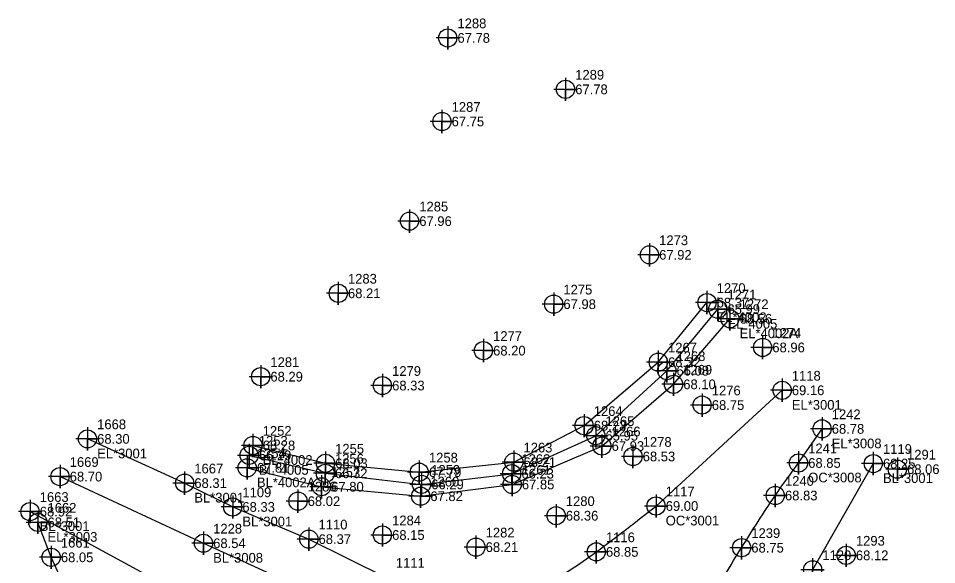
# Model space of a CAD drawing. Extents: x 2062781 to 2066835, y 358981 to 366501.
# Drawn here: x 2066377.3 to 2066613.7, y 366359.8 to 366500.5 of the extents above; entities that cross this region are included whole.
import ezdxf

# ---------------------------------------------------------------- set-up
doc = ezdxf.new("R2010")
doc.units = 0
for name, color, linetype in [('Exist DTM Breakline', 7, 'Continuous'), ('Exist DTM Breakline Cogo Comment', 7, 'Continuous'), ('Exist DTM Breakline Cogo Elevation', 7, 'Continuous'), ('Exist DTM Breakline Cogo Number', 7, 'Continuous'), ('Exist DTM Breakline Cogo Point CELL', 7, 'Continuous'), ('Exist DTM Crownline', 7, 'Continuous'), ('Exist DTM Crownline Cogo Comment', 7, 'Continuous'), ('Exist DTM Crownline Cogo Elevation', 7, 'Continuous'), ('Exist DTM Crownline Cogo Number', 7, 'Continuous'), ('Exist DTM Crownline Cogo Point CELL', 7, 'Continuous'), ('Exist DTM Regular Point CELL', 7, 'Continuous'), ('Exist DTM Regular Point Cogo Elevation', 7, 'Continuous'), ('Exist DTM Regular Point Cogo Number', 7, 'Continuous'), ('Exist DTM Ridgeline', 7, 'Continuous'), ('Exist DTM Ridgeline Cogo Comment', 7, 'Continuous'), ('Exist DTM Ridgeline Cogo Elevation', 7, 'Continuous'), ('Exist DTM Ridgeline Cogo Number', 7, 'Continuous'), ('Exist DTM Ridgeline Cogo Point CELL', 7, 'Continuous'), ('Exist Roads EOP', 7, 'Continuous'), ('Exist Roads EOP Cogo Comment', 7, 'Continuous'), ('Exist Roads EOP Cogo Elevation', 7, 'Continuous'), ('Exist Roads EOP Cogo Number', 7, 'Continuous'), ('Exist Roads EOP Cogo Point CELL', 7, 'Continuous'), ('Exist Roads EOP Other', 7, 'Continuous'), ('Exist Roads EOP Other Cogo Comment', 7, 'Continuous'), ('Exist Roads EOP Other Cogo Elevation', 7, 'Continuous'), ('Exist Roads EOP Other Cogo Number', 7, 'Continuous'), ('Exist Roads EOP Other Cogo Point CELL', 7, 'Continuous')]:
    doc.layers.add(name, color=color, linetype=linetype)

msp = doc.modelspace()

# ---------------------------------------------------------------- linework, layer by layer
at = {"layer": 'Exist DTM Breakline'}
msp.add_lwpolyline([(2066436.74, 366387.93), (2066456.35, 366383.31), (2066481.14, 366380.45), (2066504.34, 366383.21), (2066525.99, 366392.99), (2066544.27, 366409.73), (2066557.39, 366425.59)], dxfattribs=at)
at = {"layer": 'Exist DTM Breakline Cogo Point CELL'}
for points in [[(2066557.39, 366428.59), (2066557.39, 366422.59), (2066557.39, 366425.59), (2066560.39, 366425.59), (2066554.39, 366425.59)], [(2066544.27, 366412.73), (2066544.27, 366406.73), (2066544.27, 366409.73), (2066547.27, 366409.73), (2066541.27, 366409.73)], [(2066525.99, 366395.99), (2066525.99, 366389.99), (2066525.99, 366392.99), (2066528.99, 366392.99), (2066522.99, 366392.99)], [(2066436.74, 366390.93), (2066436.74, 366384.93), (2066436.74, 366387.93), (2066439.74, 366387.93), (2066433.74, 366387.93)], [(2066456.35, 366386.31), (2066456.35, 366380.31), (2066456.35, 366383.31), (2066459.35, 366383.31), (2066453.35, 366383.31)], [(2066504.34, 366386.21), (2066504.34, 366380.21), (2066504.34, 366383.21), (2066507.34, 366383.21), (2066501.34, 366383.21)], [(2066481.14, 366383.45), (2066481.14, 366377.45), (2066481.14, 366380.45), (2066484.14, 366380.45), (2066478.14, 366380.45)]]:
    msp.add_lwpolyline(points, dxfattribs=at)
for centre in [(2066557.39, 366425.59), (2066544.27, 366409.73), (2066525.99, 366392.99), (2066436.74, 366387.93), (2066456.35, 366383.31), (2066504.34, 366383.21), (2066481.14, 366380.45)]:
    msp.add_circle(centre, 2.34, dxfattribs=at)
at = {"layer": 'Exist DTM Crownline'}
msp.add_line((2066578.18, 366385.97), (2066584.24, 366394.75), dxfattribs=at)
for points in [[(2066388.06, 366382.46), (2066424.99, 366365.29)], [(2066424.99, 366365.29), (2066467.59, 366345.83), (2066505.51, 366328.48), (2066538.44, 366313.65), (2066572.05, 366298.64), (2066616.11, 366278.59), (2066645.68, 366265.08), (2066686.23, 366246.88)]]:
    msp.add_lwpolyline(points, dxfattribs=at)
msp.add_spline([(2066545.84, 366333.5), (2066552.89, 366346.31), (2066563.53, 366364.14), (2066572.2, 366377.58), (2066578.18, 366385.97)], degree=3, dxfattribs=at)
at = {"layer": 'Exist DTM Crownline Cogo Point CELL'}
for points in [[(2066584.24, 366397.75), (2066584.24, 366391.75), (2066584.24, 366394.75), (2066587.24, 366394.75), (2066581.24, 366394.75)], [(2066578.18, 366388.97), (2066578.18, 366382.97), (2066578.18, 366385.97), (2066581.18, 366385.97), (2066575.18, 366385.97)], [(2066388.06, 366385.46), (2066388.06, 366379.46), (2066388.06, 366382.46), (2066391.06, 366382.46), (2066385.06, 366382.46)], [(2066572.2, 366380.58), (2066572.2, 366374.58), (2066572.2, 366377.58), (2066575.2, 366377.58), (2066569.2, 366377.58)], [(2066424.99, 366368.29), (2066424.99, 366362.29), (2066424.99, 366365.29), (2066427.99, 366365.29), (2066421.99, 366365.29)], [(2066563.53, 366367.14), (2066563.53, 366361.14), (2066563.53, 366364.14), (2066566.53, 366364.14), (2066560.53, 366364.14)]]:
    msp.add_lwpolyline(points, dxfattribs=at)
for centre in [(2066584.24, 366394.75), (2066578.18, 366385.97), (2066388.06, 366382.46), (2066572.2, 366377.58), (2066424.99, 366365.29), (2066563.53, 366364.14)]:
    msp.add_circle(centre, 2.34, dxfattribs=at)
at = {"layer": 'Exist DTM Regular Point CELL'}
for points in [[(2066487.88, 366498.48), (2066487.88, 366492.48), (2066487.88, 366495.48), (2066490.88, 366495.48), (2066484.88, 366495.48)], [(2066518.2, 366485.23), (2066518.2, 366479.23), (2066518.2, 366482.23), (2066521.2, 366482.23), (2066515.2, 366482.23)], [(2066486.38, 366476.94), (2066486.38, 366470.94), (2066486.38, 366473.94), (2066489.38, 366473.94), (2066483.38, 366473.94)], [(2066478.05, 366451.28), (2066478.05, 366445.28), (2066478.05, 366448.28), (2066481.05, 366448.28), (2066475.05, 366448.28)], [(2066539.81, 366442.59), (2066539.81, 366436.59), (2066539.81, 366439.59), (2066542.81, 366439.59), (2066536.81, 366439.59)], [(2066459.69, 366432.68), (2066459.69, 366426.68), (2066459.69, 366429.68), (2066462.69, 366429.68), (2066456.69, 366429.68)], [(2066515.15, 366429.88), (2066515.15, 366423.88), (2066515.15, 366426.88), (2066518.15, 366426.88), (2066512.15, 366426.88)], [(2066497.06, 366417.91), (2066497.06, 366411.91), (2066497.06, 366414.91), (2066500.06, 366414.91), (2066494.06, 366414.91)], [(2066568.94, 366418.73), (2066568.94, 366412.73), (2066568.94, 366415.73), (2066571.94, 366415.73), (2066565.94, 366415.73)], [(2066439.72, 366411.2), (2066439.72, 366405.2), (2066439.72, 366408.2), (2066442.72, 366408.2), (2066436.72, 366408.2)], [(2066471.06, 366408.91), (2066471.06, 366402.91), (2066471.06, 366405.91), (2066474.06, 366405.91), (2066468.06, 366405.91)], [(2066553.36, 366403.89), (2066553.36, 366397.89), (2066553.36, 366400.89), (2066556.36, 366400.89), (2066550.36, 366400.89)], [(2066535.57, 366390.64), (2066535.57, 366384.64), (2066535.57, 366387.64), (2066538.57, 366387.64), (2066532.57, 366387.64)], [(2066603.63, 366387.36), (2066603.63, 366381.36), (2066603.63, 366384.36), (2066606.63, 366384.36), (2066600.63, 366384.36)], [(2066449.32, 366379.13), (2066449.32, 366373.13), (2066449.32, 366376.13), (2066452.32, 366376.13), (2066446.32, 366376.13)], [(2066515.78, 366375.38), (2066515.78, 366369.38), (2066515.78, 366372.38), (2066518.78, 366372.38), (2066512.78, 366372.38)], [(2066471.06, 366370.41), (2066471.06, 366364.41), (2066471.06, 366367.41), (2066474.06, 366367.41), (2066468.06, 366367.41)], [(2066495.14, 366367.28), (2066495.14, 366361.28), (2066495.14, 366364.28), (2066498.14, 366364.28), (2066492.14, 366364.28)], [(2066590.46, 366365.17), (2066590.46, 366359.17), (2066590.46, 366362.17), (2066593.46, 366362.17), (2066587.46, 366362.17)]]:
    msp.add_lwpolyline(points, dxfattribs=at)
for centre in [(2066487.88, 366495.48), (2066518.2, 366482.23), (2066486.38, 366473.94), (2066478.05, 366448.28), (2066539.81, 366439.59), (2066459.69, 366429.68), (2066515.15, 366426.88), (2066497.06, 366414.91), (2066568.94, 366415.73), (2066439.72, 366408.2), (2066471.06, 366405.91), (2066553.36, 366400.89), (2066535.57, 366387.64), (2066603.63, 366384.36), (2066449.32, 366376.13), (2066515.78, 366372.38), (2066471.06, 366367.41), (2066495.14, 366364.28), (2066590.46, 366362.17)]:
    msp.add_circle(centre, 2.34, dxfattribs=at)
at = {"layer": 'Exist DTM Ridgeline'}
for points in [[(2066437.74, 366390.48), (2066456.4, 366385.89), (2066480.54, 366383.59), (2066504.88, 366386.18), (2066522.97, 366395.58), (2066542.09, 366411.94), (2066554.62, 366427.28)], [(2066436.25, 366384.72), (2066455.38, 366379.84), (2066480.9, 366377.4), (2066504.46, 366380.42), (2066527.57, 366390.33), (2066546.01, 366406.23), (2066560.52, 366423.12)]]:
    msp.add_lwpolyline(points, dxfattribs=at)
at = {"layer": 'Exist DTM Ridgeline Cogo Point CELL'}
for points in [[(2066554.62, 366430.28), (2066554.62, 366424.28), (2066554.62, 366427.28), (2066557.62, 366427.28), (2066551.62, 366427.28)], [(2066560.52, 366426.12), (2066560.52, 366420.12), (2066560.52, 366423.12), (2066563.52, 366423.12), (2066557.52, 366423.12)], [(2066542.09, 366414.94), (2066542.09, 366408.94), (2066542.09, 366411.94), (2066545.09, 366411.94), (2066539.09, 366411.94)], [(2066546.01, 366409.23), (2066546.01, 366403.23), (2066546.01, 366406.23), (2066549.01, 366406.23), (2066543.01, 366406.23)], [(2066522.97, 366398.58), (2066522.97, 366392.58), (2066522.97, 366395.58), (2066525.97, 366395.58), (2066519.97, 366395.58)], [(2066437.74, 366393.48), (2066437.74, 366387.48), (2066437.74, 366390.48), (2066440.74, 366390.48), (2066434.74, 366390.48)], [(2066527.57, 366393.33), (2066527.57, 366387.33), (2066527.57, 366390.33), (2066530.57, 366390.33), (2066524.57, 366390.33)], [(2066456.4, 366388.89), (2066456.4, 366382.89), (2066456.4, 366385.89), (2066459.4, 366385.89), (2066453.4, 366385.89)], [(2066504.88, 366389.18), (2066504.88, 366383.18), (2066504.88, 366386.18), (2066507.88, 366386.18), (2066501.88, 366386.18)], [(2066436.25, 366387.72), (2066436.25, 366381.72), (2066436.25, 366384.72), (2066439.25, 366384.72), (2066433.25, 366384.72)], [(2066480.54, 366386.59), (2066480.54, 366380.59), (2066480.54, 366383.59), (2066483.54, 366383.59), (2066477.54, 366383.59)], [(2066455.38, 366382.84), (2066455.38, 366376.84), (2066455.38, 366379.84), (2066458.38, 366379.84), (2066452.38, 366379.84)], [(2066504.46, 366383.42), (2066504.46, 366377.42), (2066504.46, 366380.42), (2066507.46, 366380.42), (2066501.46, 366380.42)], [(2066480.9, 366380.4), (2066480.9, 366374.4), (2066480.9, 366377.4), (2066483.9, 366377.4), (2066477.9, 366377.4)]]:
    msp.add_lwpolyline(points, dxfattribs=at)
for centre in [(2066554.62, 366427.28), (2066560.52, 366423.12), (2066542.09, 366411.94), (2066546.01, 366406.23), (2066522.97, 366395.58), (2066437.74, 366390.48), (2066527.57, 366390.33), (2066436.25, 366384.72), (2066456.4, 366385.89), (2066504.88, 366386.18), (2066480.54, 366383.59), (2066455.38, 366379.84), (2066504.46, 366380.42), (2066480.9, 366377.4)]:
    msp.add_circle(centre, 2.34, dxfattribs=at)
at = {"layer": 'Exist Roads EOP'}
for p, q in [((2066541.5, 366374.88), (2066573.97, 366404.69)), ((2066420.14, 366380.78), (2066395.12, 366392.17)), ((2066597.43, 366385.81), (2066581.82, 366358.44)), ((2066380.34, 366373.44), (2066417.22, 366353.45))]:
    msp.add_line(p, q, dxfattribs=at)
for points in [[(2066420.14, 366380.78), (2066432.51, 366374.63)], [(2066432.51, 366374.63), (2066452.12, 366366.34), (2066472.03, 366356.47), (2066473.74, 366354.05)]]:
    msp.add_lwpolyline(points, dxfattribs=at)
msp.add_spline([(2066473.74, 366354.05), (2066483.78, 366350.74), (2066499.41, 366351.53), (2066512.07, 366354.63), (2066526.11, 366363.06), (2066541.5, 366374.88)], degree=3, dxfattribs=at)
at = {"layer": 'Exist Roads EOP Cogo Point CELL'}
for points in [[(2066573.97, 366407.69), (2066573.97, 366401.69), (2066573.97, 366404.69), (2066576.97, 366404.69), (2066570.97, 366404.69)], [(2066395.12, 366395.17), (2066395.12, 366389.17), (2066395.12, 366392.17), (2066398.12, 366392.17), (2066392.12, 366392.17)], [(2066597.43, 366388.81), (2066597.43, 366382.81), (2066597.43, 366385.81), (2066600.43, 366385.81), (2066594.43, 366385.81)], [(2066420.14, 366383.78), (2066420.14, 366377.78), (2066420.14, 366380.78), (2066423.14, 366380.78), (2066417.14, 366380.78)], [(2066432.51, 366377.63), (2066432.51, 366371.63), (2066432.51, 366374.63), (2066435.51, 366374.63), (2066429.51, 366374.63)], [(2066541.5, 366377.88), (2066541.5, 366371.88), (2066541.5, 366374.88), (2066544.5, 366374.88), (2066538.5, 366374.88)], [(2066380.34, 366376.44), (2066380.34, 366370.44), (2066380.34, 366373.44), (2066383.34, 366373.44), (2066377.34, 366373.44)], [(2066452.12, 366369.34), (2066452.12, 366363.34), (2066452.12, 366366.34), (2066455.12, 366366.34), (2066449.12, 366366.34)], [(2066526.11, 366366.06), (2066526.11, 366360.06), (2066526.11, 366363.06), (2066529.11, 366363.06), (2066523.11, 366363.06)], [(2066581.82, 366361.44), (2066581.82, 366355.44), (2066581.82, 366358.44), (2066584.82, 366358.44), (2066578.82, 366358.44)]]:
    msp.add_lwpolyline(points, dxfattribs=at)
for centre in [(2066573.97, 366404.69), (2066395.12, 366392.17), (2066597.43, 366385.81), (2066420.14, 366380.78), (2066541.5, 366374.88), (2066380.34, 366373.44), (2066432.51, 366374.63), (2066452.12, 366366.34), (2066526.11, 366363.06), (2066581.82, 366358.44)]:
    msp.add_circle(centre, 2.34, dxfattribs=at)
at = {"layer": 'Exist Roads EOP Other'}
msp.add_lwpolyline([(2066389.42, 366353.58), (2066389.1, 366354.32), (2066385.78, 366361.66), (2066382.35, 366370.67)], dxfattribs=at)
at = {"layer": 'Exist Roads EOP Other Cogo Point CELL'}
for points in [[(2066382.35, 366373.67), (2066382.35, 366367.67), (2066382.35, 366370.67), (2066385.35, 366370.67), (2066379.35, 366370.67)], [(2066385.78, 366364.66), (2066385.78, 366358.66), (2066385.78, 366361.66), (2066388.78, 366361.66), (2066382.78, 366361.66)]]:
    msp.add_lwpolyline(points, dxfattribs=at)
for centre in [(2066382.35, 366370.67), (2066385.78, 366361.66)]:
    msp.add_circle(centre, 2.34, dxfattribs=at)

# ---------------------------------------------------------------- texts
at = {"layer": 'Exist DTM Breakline Cogo Comment'}
for s, p in [('EL*4005', (2066559.89, 366420.59)), ('BL*4005', (2066439.24, 366382.93))]:
    msp.add_text(s, height=2.5, dxfattribs=at).set_placement(p)
at = {"layer": 'Exist DTM Breakline Cogo Elevation'}
for s, p in [('65.99', (2066559.89, 366424.34)), ('66.08', (2066546.77, 366408.48)), ('65.95', (2066528.49, 366391.74)), ('66.29', (2066439.24, 366386.68)), ('66.32', (2066458.85, 366382.06)), ('66.23', (2066506.84, 366381.96)), ('66.29', (2066483.64, 366379.2))]:
    msp.add_text(s, height=2.5, dxfattribs=at).set_placement(p)
at = {"layer": 'Exist DTM Breakline Cogo Number'}
for s, p in [('1271', (2066559.89, 366428.09)), ('1268', (2066546.77, 366412.23)), ('1265', (2066528.49, 366395.49)), ('1253', (2066439.24, 366390.43)), ('1256', (2066458.85, 366385.81)), ('1262', (2066506.84, 366385.71)), ('1259', (2066483.64, 366382.95))]:
    msp.add_text(s, height=2.5, dxfattribs=at).set_placement(p)
at = {"layer": 'Exist DTM Crownline Cogo Comment'}
for s, p in [('EL*3008', (2066586.74, 366389.75)), ('OC*3008', (2066580.68, 366380.97)), ('BL*3008', (2066427.49, 366360.29))]:
    msp.add_text(s, height=2.5, dxfattribs=at).set_placement(p)
at = {"layer": 'Exist DTM Crownline Cogo Elevation'}
for s, p in [('68.78', (2066586.74, 366393.5)), ('68.85', (2066580.68, 366384.72)), ('68.70', (2066390.56, 366381.21)), ('68.83', (2066574.7, 366376.33)), ('68.54', (2066427.49, 366364.04)), ('68.75', (2066566.03, 366362.89))]:
    msp.add_text(s, height=2.5, dxfattribs=at).set_placement(p)
at = {"layer": 'Exist DTM Crownline Cogo Number'}
for s, p in [('1242', (2066586.74, 366397.25)), ('1241', (2066580.68, 366388.47)), ('1669', (2066390.56, 366384.96)), ('1240', (2066574.7, 366380.08)), ('1228', (2066427.49, 366367.79)), ('1239', (2066566.03, 366366.64))]:
    msp.add_text(s, height=2.5, dxfattribs=at).set_placement(p)
at = {"layer": 'Exist DTM Regular Point Cogo Elevation'}
for s, p in [('67.78', (2066490.38, 366494.23)), ('67.78', (2066520.7, 366480.98)), ('67.75', (2066488.88, 366472.69)), ('67.96', (2066480.55, 366447.03)), ('67.92', (2066542.31, 366438.34)), ('68.21', (2066462.19, 366428.43)), ('67.98', (2066517.65, 366425.63)), ('68.20', (2066499.56, 366413.66)), ('68.96', (2066571.44, 366414.48)), ('68.29', (2066442.22, 366406.95)), ('68.33', (2066473.56, 366404.66)), ('68.75', (2066555.86, 366399.64)), ('68.53', (2066538.07, 366386.39)), ('68.06', (2066606.13, 366383.11)), ('68.02', (2066451.82, 366374.88)), ('68.36', (2066518.28, 366371.13)), ('68.15', (2066473.56, 366366.16)), ('68.21', (2066497.64, 366363.03)), ('68.12', (2066592.96, 366360.92))]:
    msp.add_text(s, height=2.5, dxfattribs=at).set_placement(p)
at = {"layer": 'Exist DTM Regular Point Cogo Number'}
for s, p in [('1288', (2066490.38, 366497.98)), ('1289', (2066520.7, 366484.73)), ('1287', (2066488.88, 366476.44)), ('1285', (2066480.55, 366450.78)), ('1273', (2066542.31, 366442.09)), ('1283', (2066462.19, 366432.18)), ('1275', (2066517.65, 366429.38)), ('1277', (2066499.56, 366417.41)), ('1274', (2066571.44, 366418.23)), ('1281', (2066442.22, 366410.7)), ('1279', (2066473.56, 366408.41)), ('1276', (2066555.86, 366403.39)), ('1278', (2066538.07, 366390.14)), ('1291', (2066606.13, 366386.86)), ('1286', (2066451.82, 366378.63)), ('1280', (2066518.28, 366374.88)), ('1284', (2066473.56, 366369.91)), ('1282', (2066497.64, 366366.78)), ('1293', (2066592.96, 366364.67))]:
    msp.add_text(s, height=2.5, dxfattribs=at).set_placement(p)
at = {"layer": 'Exist DTM Ridgeline Cogo Comment'}
for s, p in [('EL*4002', (2066557.12, 366422.28)), ('EL*4002A', (2066563.02, 366418.12)), ('BL*4002', (2066440.24, 366385.48)), ('BL*4002A', (2066438.75, 366379.72))]:
    msp.add_text(s, height=2.5, dxfattribs=at).set_placement(p)
at = {"layer": 'Exist DTM Ridgeline Cogo Elevation'}
for s, p in [('68.37', (2066557.12, 366426.03)), ('68.56', (2066563.02, 366421.87)), ('68.32', (2066544.59, 366410.69)), ('68.10', (2066548.51, 366404.98)), ('68.23', (2066525.47, 366394.33)), ('68.28', (2066440.24, 366389.23)), ('67.93', (2066530.07, 366389.08)), ('68.03', (2066458.9, 366384.64)), ('68.21', (2066507.38, 366384.93)), ('67.81', (2066438.75, 366383.47)), ('67.79', (2066483.04, 366382.34)), ('67.80', (2066457.88, 366378.59)), ('67.85', (2066506.96, 366379.17)), ('67.82', (2066483.4, 366376.15))]:
    msp.add_text(s, height=2.5, dxfattribs=at).set_placement(p)
at = {"layer": 'Exist DTM Ridgeline Cogo Number'}
for s, p in [('1270', (2066557.12, 366429.78)), ('1272', (2066563.02, 366425.62)), ('1267', (2066544.59, 366414.44)), ('1269', (2066548.51, 366408.73)), ('1264', (2066525.47, 366398.08)), ('1252', (2066440.24, 366392.98)), ('1266', (2066530.07, 366392.83)), ('1263', (2066507.38, 366388.68)), ('1254', (2066438.75, 366387.22)), ('1255', (2066458.9, 366388.39)), ('1258', (2066483.04, 366386.09)), ('1257', (2066457.88, 366382.34)), ('1261', (2066506.96, 366382.92)), ('1260', (2066483.4, 366379.9))]:
    msp.add_text(s, height=2.5, dxfattribs=at).set_placement(p)
at = {"layer": 'Exist Roads EOP Cogo Comment'}
for s, p in [('EL*3001', (2066576.47, 366399.69)), ('EL*3001', (2066397.62, 366387.17)), ('BL*3001', (2066599.93, 366380.81)), ('BL*3001', (2066422.64, 366375.78)), ('OC*3001', (2066544, 366369.88)), ('BL*3001', (2066382.84, 366368.44)), ('BL*3001', (2066435.01, 366369.64))]:
    msp.add_text(s, height=2.5, dxfattribs=at).set_placement(p)
at = {"layer": 'Exist Roads EOP Cogo Elevation'}
for s, p in [('69.16', (2066576.47, 366403.44)), ('68.30', (2066397.62, 366390.92)), ('68.25', (2066599.93, 366384.56)), ('68.31', (2066422.64, 366379.53)), ('68.92', (2066382.84, 366372.19)), ('68.33', (2066435.01, 366373.39)), ('69.00', (2066544, 366373.63)), ('68.37', (2066454.62, 366365.09)), ('68.85', (2066528.61, 366361.81))]:
    msp.add_text(s, height=2.5, dxfattribs=at).set_placement(p)
at = {"layer": 'Exist Roads EOP Cogo Number'}
for s, p in [('1118', (2066576.47, 366407.19)), ('1668', (2066397.62, 366394.67)), ('1119', (2066599.93, 366388.31)), ('1667', (2066422.64, 366383.28)), ('1109', (2066435.01, 366377.14)), ('1117', (2066544, 366377.38)), ('1663', (2066382.84, 366375.94)), ('1110', (2066454.62, 366368.84)), ('1116', (2066528.61, 366365.56)), ('1120', (2066584.32, 366360.94)), ('1111', (2066474.53, 366358.97))]:
    msp.add_text(s, height=2.5, dxfattribs=at).set_placement(p)
at = {"layer": 'Exist Roads EOP Other Cogo Comment'}
msp.add_text('EL*3003', height=2.5, dxfattribs=at).set_placement((2066384.85, 366365.67))
at = {"layer": 'Exist Roads EOP Other Cogo Elevation'}
for s, p in [('68.51', (2066384.85, 366369.42)), ('68.05', (2066388.28, 366360.41))]:
    msp.add_text(s, height=2.5, dxfattribs=at).set_placement(p)
at = {"layer": 'Exist Roads EOP Other Cogo Number'}
for s, p in [('1662', (2066384.85, 366373.17)), ('1661', (2066388.28, 366364.16))]:
    msp.add_text(s, height=2.5, dxfattribs=at).set_placement(p)

doc.saveas('drawing.dxf')
